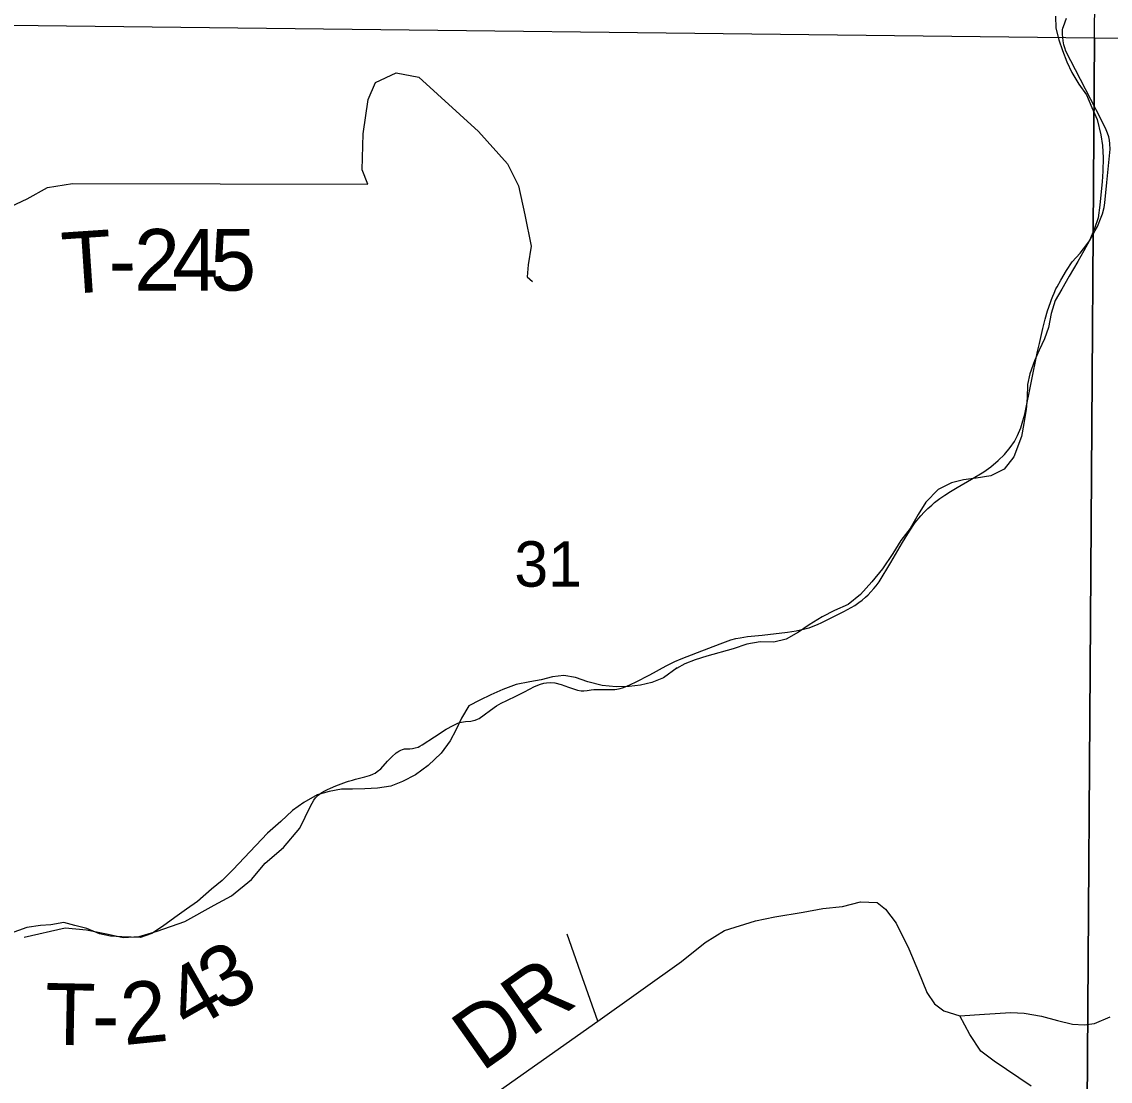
# Model space of a CAD drawing. Extents: x 2.1 to 8.9, y 14.1 to 20.9.
# Drawn here: x 6.478 to 7.48, y 19.144 to 20.12 of the extents above; entities that cross this region are included whole.
import ezdxf

# ---------------------------------------------------------------- set-up
doc = ezdxf.new("R2010")
doc.units = 0
for name, color, linetype in [('Default', 7, 'Continuous'), ('GM_X_City_Street', 7, 'Continuous'), ('GM_X_County_Road_Text', 7, 'Continuous'), ('GM_X_Interchange_Ramps', 7, 'Continuous'), ('GM_X_Minor_River', 7, 'Continuous'), ('GM_X_Minor_River_Text', 7, 'Continuous'), ('GM_X_State_Shield', 7, 'Continuous'), ('TX_P_Misc', 7, 'Continuous')]:
    doc.layers.add(name, color=color, linetype=linetype)

msp = doc.modelspace()

# ---------------------------------------------------------------- linework, layer by layer
at = {"layer": 'Default'}
for p, q in [((7.4653, 20.105), (7.4735, 20.9)), ((6.4665, 20.1167), (7.4653, 20.105))]:
    msp.add_line(p, q, dxfattribs=at)
at = {"layer": 'GM_X_City_Street'}
for p, q in [((7.4367, 20.1157), (7.4395, 20.1231)), ((7.4359, 20.1106), (7.436, 20.1124)), ((7.4359, 20.1084), (7.4359, 20.1106)), ((7.436, 20.1124), (7.4363, 20.114)), ((7.4363, 20.114), (7.4367, 20.1157)), ((7.4361, 20.1053), (7.4359, 20.1084)), ((7.4364, 20.1023), (7.4361, 20.1053)), ((7.4372, 20.0986), (7.4364, 20.1023)), ((7.438, 20.096), (7.4372, 20.0986)), ((7.4391, 20.0929), (7.438, 20.096)), ((7.4524, 20.0667), (7.4391, 20.0929)), ((6.8036, 20.0641), (6.8225, 20.0729)), ((6.8225, 20.0729), (6.8435, 20.0689)), ((6.8435, 20.0689), (6.8983, 20.019)), ((6.7968, 20.0483), (6.8036, 20.0641)), ((7.4715, 20.0299), (7.4524, 20.0667)), ((6.7921, 20.0166), (6.7968, 20.0483)), ((7.4761, 20.0203), (7.4715, 20.0299)), ((6.8983, 20.019), (6.925, 19.989)), ((7.4773, 20.0173), (7.4761, 20.0203)), ((6.7913, 19.9835), (6.7921, 20.0166)), ((7.4786, 20.0139), (7.4773, 20.0173)), ((7.4793, 20.0109), (7.4786, 20.0139)), ((7.4796, 20.0076), (7.4793, 20.0109)), ((7.4768, 19.9719), (7.4798, 20.0026)), ((7.4798, 20.0026), (7.4796, 20.0076)), ((6.925, 19.989), (6.935, 19.969)), ((6.7965, 19.9704), (6.7913, 19.9835)), ((6.5016, 19.9672), (6.5245, 19.9709)), ((6.5245, 19.9709), (6.7965, 19.9704)), ((6.935, 19.969), (6.9411, 19.9423)), ((7.475, 19.9531), (7.4768, 19.9719)), ((6.4828, 19.9569), (6.5016, 19.9672)), ((6.4579, 19.9452), (6.4828, 19.9569)), ((7.4726, 19.943), (7.4743, 19.9489)), ((7.4743, 19.9489), (7.475, 19.9531)), ((6.9411, 19.9423), (6.9469, 19.9133)), ((7.468, 19.9314), (7.4715, 19.9399)), ((7.4715, 19.9399), (7.4726, 19.943)), ((7.4661, 19.9278), (7.468, 19.9314)), ((7.4606, 19.9182), (7.4661, 19.9278)), ((6.9469, 19.9133), (6.9439, 19.8961)), ((7.4521, 19.9069), (7.4582, 19.9148)), ((7.4582, 19.9148), (7.4606, 19.9182)), ((7.4396, 19.891), (7.4449, 19.8988)), ((7.4449, 19.8988), (7.4521, 19.9069)), ((6.9439, 19.8961), (6.9432, 19.8851)), ((7.4342, 19.8819), (7.4396, 19.891)), ((6.9432, 19.8851), (6.948, 19.8807)), ((7.4309, 19.8758), (7.4342, 19.8819)), ((7.4269, 19.8673), (7.4281, 19.8701)), ((7.4281, 19.8701), (7.4298, 19.8739)), ((7.4298, 19.8739), (7.4309, 19.8758)), ((7.4222, 19.8539), (7.4247, 19.8614)), ((7.4247, 19.8614), (7.4258, 19.8643)), ((7.4258, 19.8643), (7.4269, 19.8673)), ((7.4199, 19.846), (7.4222, 19.8539)), ((7.4178, 19.8375), (7.4193, 19.8435)), ((7.4193, 19.8435), (7.4199, 19.846)), ((7.4146, 19.8237), (7.4178, 19.8375)), ((7.413, 19.8163), (7.4146, 19.8237)), ((7.4011, 19.7586), (7.413, 19.8163)), ((7.3995, 19.7524), (7.4011, 19.7586)), ((7.3976, 19.746), (7.3995, 19.7524)), ((7.3916, 19.7335), (7.3946, 19.739)), ((7.3946, 19.739), (7.3976, 19.746)), ((7.3877, 19.7278), (7.3916, 19.7335)), ((7.3767, 19.7159), (7.3824, 19.7216)), ((7.3824, 19.7216), (7.3877, 19.7278)), ((7.3634, 19.7055), (7.37, 19.7102)), ((7.37, 19.7102), (7.3767, 19.7159)), ((7.3388, 19.691), (7.3521, 19.6988)), ((7.3521, 19.6988), (7.3634, 19.7055)), ((7.3327, 19.6875), (7.3388, 19.691)), ((7.3182, 19.6772), (7.3231, 19.6809)), ((7.3231, 19.6809), (7.3276, 19.6841)), ((7.3276, 19.6841), (7.3327, 19.6875)), ((7.3055, 19.6651), (7.3085, 19.6683)), ((7.3085, 19.6683), (7.312, 19.6718)), ((7.312, 19.6718), (7.3155, 19.6749)), ((7.3155, 19.6749), (7.3182, 19.6772)), ((7.295, 19.6508), (7.3004, 19.6588)), ((7.3004, 19.6588), (7.3055, 19.6651)), ((7.2886, 19.6404), (7.295, 19.6508)), ((7.2778, 19.622), (7.2886, 19.6404)), ((7.267, 19.6042), (7.2778, 19.622)), ((7.2596, 19.5951), (7.2622, 19.598)), ((7.2622, 19.598), (7.2645, 19.6007)), ((7.2645, 19.6007), (7.267, 19.6042)), ((7.2514, 19.5874), (7.2546, 19.5901)), ((7.2546, 19.5901), (7.2569, 19.5923)), ((7.2569, 19.5923), (7.2596, 19.5951)), ((7.2345, 19.577), (7.2447, 19.5825)), ((7.2447, 19.5825), (7.2485, 19.5851)), ((7.2485, 19.5851), (7.2514, 19.5874)), ((7.2145, 19.5669), (7.2235, 19.5715)), ((7.2235, 19.5715), (7.2345, 19.577)), ((7.1593, 19.5552), (7.1828, 19.558)), ((7.1828, 19.558), (7.1907, 19.5593)), ((7.1907, 19.5593), (7.1947, 19.56)), ((7.1947, 19.56), (7.1975, 19.5606)), ((7.1975, 19.5606), (7.2012, 19.5616)), ((7.2012, 19.5616), (7.2027, 19.562)), ((7.2027, 19.562), (7.2034, 19.5623)), ((7.2034, 19.5623), (7.2103, 19.565)), ((7.2103, 19.565), (7.2145, 19.5669)), ((7.1207, 19.5473), (7.1306, 19.5508)), ((7.1306, 19.5508), (7.1352, 19.552)), ((7.1352, 19.552), (7.1391, 19.5528)), ((7.1391, 19.5528), (7.1458, 19.5538)), ((7.1458, 19.5538), (7.1593, 19.5552)), ((7.0848, 19.5333), (7.0998, 19.5391)), ((7.0998, 19.5391), (7.1207, 19.5473)), ((7.071, 19.5268), (7.0789, 19.5308)), ((7.0789, 19.5308), (7.0848, 19.5333)), ((7.0429, 19.5118), (7.056, 19.5188)), ((7.056, 19.5188), (7.071, 19.5268)), ((6.9498, 19.5078), (6.9554, 19.51)), ((6.9554, 19.51), (6.9585, 19.5109)), ((6.9585, 19.5109), (6.961, 19.5113)), ((6.961, 19.5113), (6.9642, 19.5115)), ((6.9642, 19.5115), (6.9687, 19.5113)), ((6.9687, 19.5113), (6.9745, 19.5097)), ((6.9745, 19.5097), (6.981, 19.5074)), ((7.031, 19.5068), (7.035, 19.5082)), ((7.035, 19.5082), (7.0429, 19.5118)), ((6.9243, 19.4951), (6.9333, 19.4992)), ((6.9333, 19.4992), (6.9405, 19.5029)), ((6.9405, 19.5029), (6.9498, 19.5078)), ((6.981, 19.5074), (6.9893, 19.5044)), ((6.9893, 19.5044), (6.9927, 19.5038)), ((6.9927, 19.5038), (6.9953, 19.5038)), ((6.9953, 19.5038), (6.9984, 19.5041)), ((6.9984, 19.5041), (7.002, 19.5049)), ((7.002, 19.5049), (7.0046, 19.5053)), ((7.0046, 19.5053), (7.0076, 19.5053)), ((7.0076, 19.5053), (7.0137, 19.505)), ((7.0137, 19.505), (7.0193, 19.505)), ((7.0193, 19.505), (7.0237, 19.5053)), ((7.0237, 19.5053), (7.0256, 19.5055)), ((7.0256, 19.5055), (7.0286, 19.5061)), ((7.0286, 19.5061), (7.031, 19.5068)), ((6.9095, 19.4862), (6.915, 19.4901)), ((6.915, 19.4901), (6.9193, 19.4926)), ((6.9193, 19.4926), (6.9243, 19.4951)), ((6.8951, 19.4769), (6.8974, 19.4778)), ((6.8974, 19.4778), (6.899, 19.4785)), ((6.899, 19.4785), (6.9036, 19.4817)), ((6.9036, 19.4817), (6.9095, 19.4862)), ((6.8577, 19.4617), (6.8684, 19.4685)), ((6.8684, 19.4685), (6.8749, 19.472)), ((6.8749, 19.472), (6.8786, 19.4738)), ((6.8786, 19.4738), (6.8807, 19.4747)), ((6.8807, 19.4747), (6.8826, 19.4752)), ((6.8826, 19.4752), (6.8864, 19.4757)), ((6.8864, 19.4757), (6.8914, 19.4761)), ((6.8914, 19.4761), (6.8938, 19.4765)), ((6.8938, 19.4765), (6.8951, 19.4769)), ((6.8464, 19.4541), (6.8577, 19.4617)), ((6.8226, 19.4467), (6.824, 19.4478)), ((6.824, 19.4478), (6.825, 19.4485)), ((6.825, 19.4485), (6.8269, 19.4494)), ((6.8269, 19.4494), (6.8285, 19.45)), ((6.8285, 19.45), (6.8303, 19.4504)), ((6.8303, 19.4504), (6.8313, 19.4505)), ((6.8313, 19.4505), (6.8327, 19.4506)), ((6.8327, 19.4506), (6.835, 19.4506)), ((6.835, 19.4506), (6.8374, 19.4509)), ((6.8374, 19.4509), (6.8401, 19.4514)), ((6.8401, 19.4514), (6.8427, 19.4521)), ((6.8427, 19.4521), (6.8444, 19.4529)), ((6.8444, 19.4529), (6.8464, 19.4541)), ((6.8084, 19.4322), (6.8145, 19.4391)), ((6.8145, 19.4391), (6.8186, 19.4432)), ((6.8186, 19.4432), (6.8226, 19.4467)), ((6.8017, 19.4274), (6.8032, 19.4282)), ((6.8032, 19.4282), (6.8049, 19.4295)), ((6.8049, 19.4295), (6.8084, 19.4322)), ((6.767, 19.4165), (6.7718, 19.4184)), ((6.7718, 19.4184), (6.7744, 19.4193)), ((6.7744, 19.4193), (6.7769, 19.4201)), ((6.7769, 19.4201), (6.7785, 19.4206)), ((6.7785, 19.4206), (6.7822, 19.4216)), ((6.7822, 19.4216), (6.785, 19.4225)), ((6.785, 19.4225), (6.7887, 19.4234)), ((6.7887, 19.4234), (6.7938, 19.4247)), ((6.7938, 19.4247), (6.798, 19.426)), ((6.798, 19.426), (6.8003, 19.4268)), ((6.8003, 19.4268), (6.8017, 19.4274)), ((6.7484, 19.4055), (6.7508, 19.408)), ((6.7508, 19.408), (6.7541, 19.4103)), ((6.7541, 19.4103), (6.7561, 19.4114)), ((6.7561, 19.4114), (6.7592, 19.413)), ((6.7592, 19.413), (6.7622, 19.4144)), ((6.7622, 19.4144), (6.767, 19.4165)), ((6.7338, 19.3774), (6.7436, 19.3976)), ((6.7436, 19.3976), (6.7468, 19.4032)), ((6.7468, 19.4032), (6.7484, 19.4055)), ((6.7189, 19.3597), (6.7338, 19.3774)), ((6.7019, 19.3453), (6.7189, 19.3597)), ((6.6892, 19.3302), (6.7019, 19.3453)), ((6.671, 19.3152), (6.6892, 19.3302)), ((6.6549, 19.3067), (6.671, 19.3152)), ((6.6279, 19.2916), (6.6549, 19.3067)), ((6.6025, 19.2827), (6.6279, 19.2916)), ((6.4801, 19.2772), (6.5177, 19.2857)), ((6.5177, 19.2857), (6.5376, 19.2839)), ((6.5376, 19.2839), (6.5575, 19.2799)), ((6.5575, 19.2799), (6.5713, 19.2768)), ((6.5713, 19.2768), (6.586, 19.2776)), ((6.586, 19.2776), (6.6025, 19.2827)), ((6.9922, 19.2449), (6.9799, 19.28)), ((7.0081, 19.1998), (6.9922, 19.2449)), ((7.3506, 19.1874), (7.3414, 19.2048)), ((7.3607, 19.1723), (7.3506, 19.1874)), ((7.3729, 19.1629), (7.3607, 19.1723)), ((7.4069, 19.1398), (7.3729, 19.1629))]:
    msp.add_line(p, q, dxfattribs=at)
at = {"layer": 'GM_X_Interchange_Ramps'}
for p, q in [((6.4665, 20.1167), (7.4653, 20.105)), ((7.4653, 20.105), (7.4585, 19.1081)), ((7.4585, 19.1081), (7.4653, 20.105)), ((7.4653, 20.105), (8.4603, 20.0986))]:
    msp.add_line(p, q, dxfattribs=at)
at = {"layer": 'GM_X_State_Shield'}
for p, q in [((7.2333, 19.3055), (7.25, 19.3098)), ((7.25, 19.3098), (7.2652, 19.309)), ((7.2652, 19.309), (7.273, 19.3028)), ((7.1711, 19.2958), (7.1971, 19.3001)), ((7.1971, 19.3001), (7.2154, 19.3036)), ((7.2154, 19.3036), (7.2333, 19.3055)), ((7.273, 19.3028), (7.2827, 19.29)), ((7.1248, 19.2834), (7.1532, 19.2923)), ((7.1532, 19.2923), (7.1711, 19.2958)), ((7.2827, 19.29), (7.2943, 19.2663)), ((7.1069, 19.2721), (7.1248, 19.2834)), ((7.0851, 19.2546), (7.1069, 19.2721)), ((7.2943, 19.2663), (7.3033, 19.2453)), ((7.0081, 19.1998), (7.0851, 19.2546)), ((7.3033, 19.2453), (7.3107, 19.2272)), ((7.3107, 19.2272), (7.3111, 19.2262)), ((7.3111, 19.2262), (7.3181, 19.2157)), ((7.3181, 19.2157), (7.3265, 19.2094)), ((7.3265, 19.2094), (7.3414, 19.2048)), ((7.364, 19.2062), (7.3883, 19.2077)), ((7.3883, 19.2077), (7.4007, 19.2072)), ((6.8946, 19.1198), (7.0081, 19.1998)), ((7.3414, 19.2048), (7.364, 19.2062)), ((7.4007, 19.2072), (7.4166, 19.2044)), ((7.4166, 19.2044), (7.4312, 19.2005)), ((7.4312, 19.2005), (7.4452, 19.1969)), ((7.4557, 19.1963), (7.4653, 19.1976)), ((7.4653, 19.1976), (7.4798, 19.2037)), ((7.4452, 19.1969), (7.4557, 19.1963))]:
    msp.add_line(p, q, dxfattribs=at)
at = {"layer": 'TX_P_Misc'}
for p, q in [((7.4295, 20.125), (7.4298, 20.1139)), ((7.4298, 20.1139), (7.4324, 20.1034)), ((7.4324, 20.1034), (7.436, 20.0936)), ((7.436, 20.0936), (7.4398, 20.083)), ((7.4398, 20.083), (7.4446, 20.0733)), ((7.4446, 20.0733), (7.451, 20.0624)), ((7.451, 20.0624), (7.4581, 20.0527)), ((7.4581, 20.0527), (7.4629, 20.0411)), ((7.4629, 20.0411), (7.4678, 20.0298)), ((7.4678, 20.0298), (7.4712, 20.0158)), ((7.4712, 20.0158), (7.4726, 20.0059)), ((7.4726, 20.0059), (7.4733, 19.9946)), ((7.4733, 19.9946), (7.4729, 19.9824)), ((7.4729, 19.9824), (7.4724, 19.9725)), ((7.4724, 19.9725), (7.4712, 19.9607)), ((7.4712, 19.9607), (7.4703, 19.9511)), ((7.4703, 19.9511), (7.4688, 19.9393)), ((7.4688, 19.9393), (7.4652, 19.9297)), ((7.4652, 19.9297), (7.4606, 19.9185)), ((7.4555, 19.9089), (7.4501, 19.8992)), ((7.4606, 19.9185), (7.4555, 19.9089)), ((7.4501, 19.8992), (7.4421, 19.8857)), ((7.4421, 19.8857), (7.4352, 19.8737)), ((7.4352, 19.8737), (7.429, 19.8633)), ((7.429, 19.8633), (7.4256, 19.8514)), ((7.4256, 19.8514), (7.4229, 19.8384)), ((7.4229, 19.8384), (7.4194, 19.828)), ((7.4194, 19.828), (7.4143, 19.8176)), ((7.4143, 19.8176), (7.41, 19.8076)), ((7.41, 19.8076), (7.4058, 19.7957)), ((7.4058, 19.7957), (7.4038, 19.7858)), ((7.4038, 19.7858), (7.4034, 19.7736)), ((7.4034, 19.7736), (7.4025, 19.7629)), ((7.4025, 19.7629), (7.4002, 19.7499)), ((7.4002, 19.7499), (7.3982, 19.7381)), ((7.3982, 19.7381), (7.3912, 19.7193)), ((7.3912, 19.7193), (7.3823, 19.708)), ((7.3446, 19.6982), (7.3337, 19.6953)), ((7.3564, 19.6997), (7.3446, 19.6982)), ((7.37, 19.702), (7.3564, 19.6997)), ((7.3823, 19.708), (7.37, 19.702)), ((7.3213, 19.6892), (7.3102, 19.6775)), ((7.3337, 19.6953), (7.3213, 19.6892)), ((7.3102, 19.6775), (7.3029, 19.6663)), ((7.3029, 19.6663), (7.2957, 19.6535)), ((7.2957, 19.6535), (7.2872, 19.6423)), ((7.2872, 19.6423), (7.2796, 19.6303)), ((7.2796, 19.6303), (7.2701, 19.6163)), ((7.2701, 19.6163), (7.2605, 19.6043)), ((7.2605, 19.6043), (7.2498, 19.5926)), ((7.2498, 19.5926), (7.2387, 19.5835)), ((7.2387, 19.5835), (7.2259, 19.5779)), ((7.2147, 19.5722), (7.2027, 19.5647)), ((7.2259, 19.5779), (7.2147, 19.5722)), ((7.193, 19.558), (7.1814, 19.5516)), ((7.2027, 19.5647), (7.193, 19.558)), ((7.1575, 19.549), (7.1454, 19.5468)), ((7.1701, 19.5486), (7.1575, 19.549)), ((7.1814, 19.5516), (7.1701, 19.5486)), ((7.1326, 19.5426), (7.1085, 19.5359)), ((7.1454, 19.5468), (7.1326, 19.5426)), ((7.0881, 19.5289), (7.0806, 19.5246)), ((7.0979, 19.5326), (7.0881, 19.5289)), ((7.1085, 19.5359), (7.0979, 19.5326)), ((6.9769, 19.5179), (6.9663, 19.5168)), ((6.9876, 19.5163), (6.9769, 19.5179)), ((7.0811, 19.525), (7.0686, 19.5158)), ((6.933, 19.5096), (6.9206, 19.5051)), ((6.9455, 19.5123), (6.933, 19.5096)), ((6.9561, 19.5142), (6.9455, 19.5123)), ((6.9663, 19.5168), (6.9561, 19.5142)), ((6.9991, 19.5121), (6.9876, 19.5163)), ((7.0121, 19.5087), (6.9991, 19.5121)), ((7.0251, 19.5076), (7.0121, 19.5087)), ((7.0369, 19.508), (7.0251, 19.5076)), ((7.0475, 19.509), (7.0369, 19.508)), ((7.058, 19.5117), (7.0475, 19.509)), ((7.0686, 19.5158), (7.058, 19.5117)), ((6.9097, 19.5002), (6.8996, 19.4953)), ((6.9206, 19.5051), (6.9097, 19.5002)), ((6.8895, 19.49), (6.8827, 19.4788)), ((6.8996, 19.4953), (6.8895, 19.49)), ((6.8827, 19.4788), (6.8773, 19.4676)), ((6.8723, 19.4579), (6.8639, 19.4466)), ((6.8773, 19.4676), (6.8723, 19.4579)), ((6.8639, 19.4466), (6.8521, 19.4352)), ((6.8521, 19.4352), (6.8402, 19.4265)), ((6.8282, 19.4204), (6.8177, 19.4163)), ((6.8402, 19.4265), (6.8282, 19.4204)), ((6.7499, 19.4081), (6.7376, 19.4012)), ((6.7608, 19.4111), (6.7499, 19.4081)), ((6.7722, 19.4133), (6.7608, 19.4111)), ((6.7824, 19.4133), (6.7722, 19.4133)), ((6.7938, 19.4136), (6.7824, 19.4133)), ((6.8052, 19.4144), (6.7938, 19.4136)), ((6.8177, 19.4163), (6.8052, 19.4144)), ((6.7376, 19.4012), (6.7272, 19.3937)), ((6.7272, 19.3937), (6.7165, 19.3835)), ((6.7165, 19.3835), (6.7042, 19.3728)), ((6.7042, 19.3728), (6.6932, 19.3614)), ((6.6932, 19.3614), (6.6722, 19.3391)), ((6.6722, 19.3391), (6.6623, 19.3293)), ((6.6623, 19.3293), (6.6526, 19.3214)), ((6.6526, 19.3214), (6.6397, 19.31)), ((6.6397, 19.31), (6.6296, 19.3028)), ((6.6296, 19.3028), (6.6189, 19.2952)), ((6.4951, 19.2879), (6.4826, 19.286)), ((6.5046, 19.2886), (6.4951, 19.2879)), ((6.5167, 19.2905), (6.5046, 19.2886)), ((6.5267, 19.2878), (6.5167, 19.2905)), ((6.5378, 19.2851), (6.5267, 19.2878)), ((6.6189, 19.2952), (6.6073, 19.2869)), ((6.4826, 19.286), (6.4672, 19.2806)), ((6.5494, 19.2801), (6.5378, 19.2851)), ((6.5597, 19.2782), (6.5494, 19.2801)), ((6.57, 19.2774), (6.5597, 19.2782)), ((6.5871, 19.2767), (6.57, 19.2774)), ((6.5976, 19.2805), (6.5871, 19.2767)), ((6.6073, 19.2869), (6.5976, 19.2805))]:
    msp.add_line(p, q, dxfattribs=at)

# ---------------------------------------------------------------- texts
at = {"layer": 'GM_X_County_Road_Text'}
msp.add_text('31', height=0.04186, rotation=0, dxfattribs=at).set_placement((6.9313, 19.5998))
at = {"layer": 'GM_X_Minor_River'}
msp.add_text('DR', height=0.05682, rotation=35.1941, dxfattribs=at).set_placement((6.9013, 19.1526))
at = {"layer": 'GM_X_Minor_River_Text'}
for s, rotation, p in [('T', 3.8557, (6.5166, 19.869)), ('2', 0.2498, (6.5814, 19.8722)), ('4', 0.0416, (6.6164, 19.8724)), ('5', 0.0052, (6.6513, 19.8724)), ('-', 0.8275, (6.5582, 19.8719)), ('3', 30.314, (6.6623, 19.2067)), ('4', 29.6742, (6.6313, 19.1891)), ('2', 5.8481, (6.5722, 19.1777)), ('T', 358.8857, (6.4988, 19.1782)), ('-', 359.9076, (6.5424, 19.1774))]:
    msp.add_text(s, height=0.0568, rotation=rotation, dxfattribs=at).set_placement(p)

doc.saveas('drawing.dxf')
